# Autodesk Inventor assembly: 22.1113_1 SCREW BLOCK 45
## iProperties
Created: 2008-12
Part Number: 22.1113_1 SCREW BLOCK 45
Document SubType Name: Assembly
Designer: Administrator
Author: Administrator
